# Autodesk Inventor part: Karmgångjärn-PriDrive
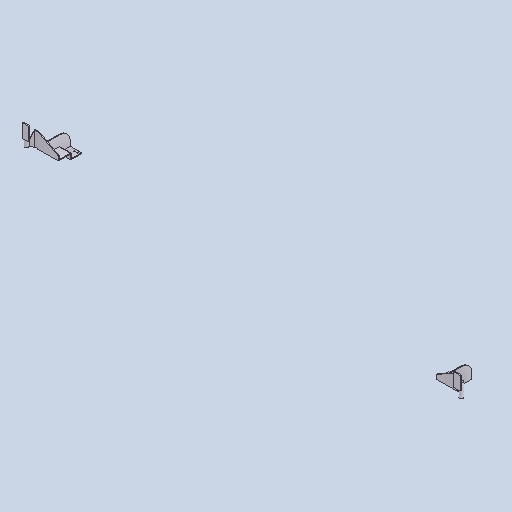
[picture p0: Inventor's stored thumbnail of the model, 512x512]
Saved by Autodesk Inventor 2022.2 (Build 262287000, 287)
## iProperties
Created: 2019-06
Part Number: Karmgångjärn-PriDrive
Material: Aluminum 6061, Welded
Document SubType Name: Modeling
Designer: cl
Density: 2.7 g/cm^3
Appearance: Weld - Aluminum
Author: cl
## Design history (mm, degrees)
sketch "Sketch1"
  geometry: L1 (0, 8)-(225, 8); L2 (228.071, 0)-(0, 0); L3 (0, 0)-(0, 8); L4 (225, 8)-(252.016, 32.325); L5 (225, 8)-(236.561, 8); L6 (228.071, 0)-(257.369, 26.38); L7 (252.016, 32.325)-(257.369, 26.38); C1 r 17.5 at (270, 40); 2 further points
  constraints: 14 end point, 2 coincident, 2 horizontal, 2 parallel, 1 centre point, 1 vertical
  dimensions: "d0" = 35 diameter of C1; "d1" = 40 vertical distance of point (0, 0) C1.centre; "d2" = 270 horizontal distance of point (0, 0) C1.centre; "d3" = 42 deg angle of L5 L4; "d4" = 8 distance between parallel lines of L4 L6; "d5" = 8 distance between parallel lines of L1 L2; "d6" = 225 horizontal distance of point (0, 0) L1.end; "d7" = 1 distance edge to line of C1 L7; "d8" = 90 deg angle of L4 L7; "d10" = 27.76238 distance from line of L5.end L7
extrude "Extrusion1" new body sketch "Sketch1" distance "d11" = 140; taper "d12" = 0 deg
thicken "Thicken1" dims "d13" = 10, "d14" = 80
chamfer "Chamfer1" distance "d15" = 100; stored, may be unused: second distance "d16" = 188.071, angle "d17" = 45 deg
sketch "Sketch2"
  geometry: L1 (-36.354, 140)-(-63.797, 140) reference; L2 (-36.354, 140)-(0, 56); L3 (0, 0)-(0, 140) reference; L4 (0, 140)-(-36.354, 140) reference; L5 (0, 56)-(0, 140); L6 (0, 140)-(-36.354, 140); 1 further point
  constraints: 6 end point, 1 perpendicular, 1 point on line, 1 vertical
  dimensions: "d18" = 56 distance of L3.start L2.end
extrude "Extrusion2" cut sketch "Sketch2" extent not by distance; stored distance "d19" = 29.794; taper "d20" = 0 deg
workplane "Work Plane1"
sketch "Sketch3"
  geometry: L1 (-57.5, 200)-(2.5, 200); L2 (2.5, 200)-(2.5, 70); L3 (2.5, 70)-(-57.5, 70); L4 (-57.5, 70)-(-57.5, 200); L5 (-62.5, 130)-(-27.5, 130) reference; L6 (-27.5, 0)-(-62.5, 0) reference; 1 further point
  constraints: 8 end point, 2 parallel, 1 horizontal, 1 perpendicular
  dimensions: "d22" = 5 distance from line of L5.start L4; "d23" = 60 distance of L1.start L1.end; "d24" = 130 distance of L3.end L1.start; "d25" = 70 distance between parallel lines of L1 L5
extrude "Extrusion3" join sketch "Sketch3" distance "d26" = 10; taper "d27" = 0 deg
sketch "Sketch4"
  geometry: L1 (-225, 8)-(0, 8) reference; L2 (0, 8)-(-198.421, 8); L3 (-115, -91.704)-(-115, -111.704); L4 (-115, -111.704)-(0, -111.704); L5 (0, -111.704)-(0, 8); L6 (-198.421, 8)-(-115, -91.704); 1 further point
  constraints: 10 end point, 2 parallel, 1 horizontal, 1 perpendicular, 1 point on line
  dimensions: "d29" = 115 distance of L3.end L4.end; "d33" = 83.42111 distance from line of L2.end L3; "d62" = 130 distance of L2.end L3.start; "d63" = 20 distance of L3.start L3.end
extrude "Extrusion4" join sketch "Sketch4" stored distance "d35" = 8; taper "d36" = 0 deg
fillet "Fillet1" dims "d37" = 2
sketch "Sketch5"
  geometry: L1 (81.748, 0)-(0, 0) reference; L2 (0, 0)-(-115, 0); L3 (-115, 0)-(-115, -50); L4 (-115, -50)-(0, -50); L5 (0, -50)-(0, 0); L6 (-115, 8)-(-115, 0) reference
  constraints: 8 end point, 2 parallel, 1 collinear, 1 horizontal, 1 perpendicular
  dimensions: "d64" = 50 distance of L3.end L2.end
extrude "Extrusion5" join sketch "Sketch5" distance "d39" = 8; taper "d40" = 0 deg
sketch "Sketch6"
  geometry: L1 (115, -247.408)-(0, -247.408) reference; L2 (0, -247.408)-(115, -247.408); L3 (115, -247.408)-(115, -342.408); L4 (115, -342.408)-(0, -342.408); L5 (0, -342.408)-(0, -247.408); L6 (115, -239.408)-(115, -247.408) reference; 2 further points
  constraints: 8 end point, 2 parallel, 1 collinear, 1 horizontal, 1 perpendicular
  dimensions: "d65" = 95 distance of L2.end L3.end
extrude "Extrusion6" join sketch "Sketch6" distance "d42" = 8; taper "d43" = 0 deg
fillet "Fillet2" dims "d44" = 4
sketch "Sketch7"
  geometry: L1 (-91.704, -8)-(-91.704, -105.147) reference; L2 (-91.704, -105.147)-(-99.704, -105.147) reference; L3 (-99.704, -105.147)-(-99.704, -2) reference; L4 (-97.704, 0)-(0, 0) reference; L5 (0, 0)-(20, 0) reference; L6 (20, 0)-(20, -4) reference; L7 (16, -8)-(0, -8) reference; L8 (0, 0)-(0, -8) reference; L9 (0, -8)-(-91.704, -8) reference; L10 (20, 0)-(20, 50) reference; L11 (20, 50)-(123, 50) reference; L12 (28, 42)-(28, 0) reference; L13 (28, 0)-(20, 0) reference; L14 (123, 50)-(123, 42) reference; L15 (123, 42)-(28, 42) reference; L16 (-91.704, -4)-(-91.704, -144) reference; L17 (-91.704, -103)-(123, -103); L18 (28, 42)-(123, 42) reference; L19 (123, -103)-(123, 42); A1 r 2 centre (-97.704, -2) between (-97.704, 0) and (-99.704, -2) reference; A2 r 4 centre (16, -4) between (16, -8) and (20, -4) reference; 1 further point
  constraints: 4 end point, 1 horizontal, 1 perpendicular, 1 point on line
  dimensions: "d66" = 145 distance of L17.end L14.end
extrude "Extrusion7" join sketch "Sketch7" distance "d46" = 8; taper "d47" = 0 deg
fillet "Fillet3" dims "d48" = 100
sketch "Sketch8"
  geometry: L1 (0, -342.408)-(115, -342.408) reference; L2 (115, -239.408)-(115, -342.408) reference; 3 further points
  dimensions: "d68" = 20 distance from line of L1 point (95, -322.408); "d69" = 0 vertical distance of point (95, -322.408) point (70, -322.408); "d70" = 25 distance of point (95, -322.408) point (70, -322.408); "d71" = 20 distance from line of L2 point (95, -322.408); "d72" = 40 horizontal distance of point (30, -287.408) point (70, -322.408); "d73" = 35 vertical distance of point (70, -322.408) point (30, -287.408)
hole "Hole1" sketch "Sketch8" at (30, -287.408), (70, -322.408), (95, -322.408) diameter "d55" = 12; stored, may be unused: countersink angle "d59" = 90 deg, drill point angle "d61" = 118 deg; dims "d56" = 6, "d57" = 4, "d58" = 2, "d60" = 8
workplane "Work Plane2"
mirror "Mirror1"
body "Solid1"
node "Projected Loop1"
node "Project Cut Edges1"
other parameters: "d21" = 57, "BladBredd" = 987.5, "Fönsterhöjd" = 862, "d74" = 2025.01 (computed from DagBredd)
